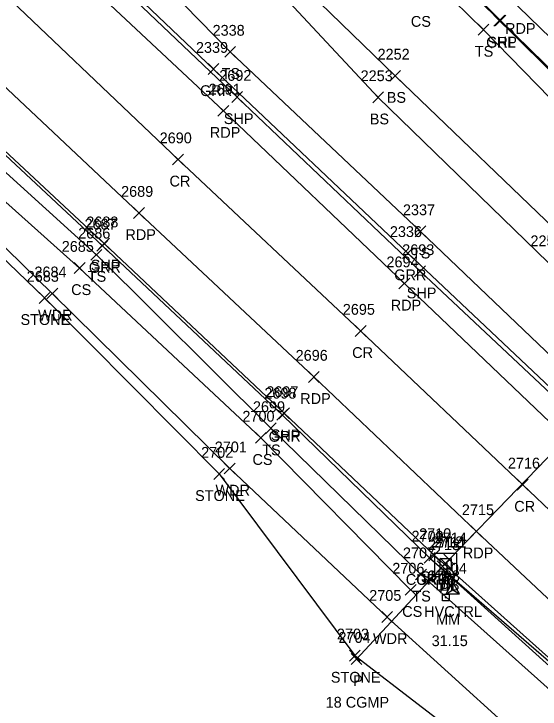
# Model space of a CAD drawing. Extents: x 1647574 to 1652703, y 212895 to 228670.
# Drawn here: x 1648450.4 to 1648547.8, y 227486.1 to 227614.7 of the extents above; entities that cross this region are included whole.
import ezdxf

# ---------------------------------------------------------------- set-up
doc = ezdxf.new("R2010")
doc.units = 0
for name, color, linetype in [('C_A', 7, 'Continuous'), ('C_I', 7, 'Continuous'), ('CPSM', 7, 'Continuous'), ('D_A', 7, 'Continuous'), ('D_C', 7, 'Continuous'), ('D_I', 7, 'Continuous'), ('D_TIC', 7, 'Continuous'), ('DCP', 7, 'Continuous'), ('DS', 7, 'Continuous'), ('L_A', 7, 'Continuous'), ('L_I', 7, 'Continuous'), ('L_TIC', 7, 'Continuous'), ('LASF', 7, 'Continuous'), ('LAWA', 7, 'Continuous'), ('LELB', 7, 'Continuous'), ('P_A', 7, 'Continuous'), ('P_I', 7, 'Continuous'), ('P_TIC', 7, 'Continuous'), ('PET', 7, 'Continuous'), ('PRC', 7, 'Continuous'), ('PSP', 7, 'Continuous'), ('R_A', 7, 'Continuous'), ('R_I', 7, 'Continuous'), ('R_TIC', 7, 'Continuous'), ('RC', 7, 'Continuous'), ('RGR', 7, 'Continuous'), ('S_A', 7, 'Continuous'), ('S_C', 7, 'Continuous'), ('S_I', 7, 'Continuous'), ('SRM', 7, 'Continuous')]:
    doc.layers.add(name, color=color, linetype=linetype)

msp = doc.modelspace()

# ---------------------------------------------------------------- linework, layer by layer
at = {"layer": 'CPSM'}
for p, q in [((1648530.44, 227507.4), (1648531.69, 227509.56)), ((1648532.94, 227507.4), (1648531.69, 227509.56)), ((1648531.69, 227508.12), (1648531.69, 227509.56)), ((1648530.44, 227507.4), (1648531.69, 227508.12)), ((1648530.44, 227507.4), (1648532.94, 227507.4)), ((1648531.69, 227508.12), (1648531.69, 227508.12)), ((1648531.69, 227508.12), (1648532.94, 227507.4))]:
    msp.add_line(p, q, dxfattribs=at)
at = {"layer": 'D_TIC'}
for points in [[(1648529.35, 227512.03), (1648531.35, 227514.03)], [(1648531.35, 227512.03), (1648529.35, 227514.03)], [(1648530, 227512.75), (1648532, 227514.75)], [(1648532, 227512.75), (1648530, 227514.75)], [(1648528.77, 227511.49), (1648530.77, 227513.49)], [(1648530.77, 227511.49), (1648528.77, 227513.49)], [(1648512.84, 227494.33), (1648514.84, 227496.33)], [(1648514.84, 227494.33), (1648512.84, 227496.33)]]:
    msp.add_lwpolyline(points, dxfattribs=at)
at = {"layer": 'DCP'}
for points in [[(1648568.95, 227553.01), (1648531, 227513.75)], [(1648513.84, 227495.33), (1648529.77, 227512.49)]]:
    msp.add_lwpolyline(points, dxfattribs=at)
at = {"layer": 'DS'}
for p, q in [((1648528.35, 227514.96), (1648532.35, 227514.96)), ((1648528.35, 227510.96), (1648528.35, 227514.96)), ((1648529.35, 227511.96), (1648529.35, 227513.96)), ((1648529.35, 227513.96), (1648531.35, 227513.96)), ((1648531.35, 227513.96), (1648531.35, 227511.96)), ((1648532.35, 227514.96), (1648532.35, 227510.96)), ((1648530.36, 227512.96), (1648530.36, 227512.96)), ((1648530.36, 227512.96), (1648530.36, 227512.96)), ((1648531.35, 227511.96), (1648529.35, 227511.96)), ((1648532.35, 227510.96), (1648528.35, 227510.96))]:
    msp.add_line(p, q, dxfattribs=at)
at = {"layer": 'L_TIC'}
for points in [[(1648536.34, 227610.83), (1648538.34, 227612.83)], [(1648538.34, 227610.83), (1648536.34, 227612.83)], [(1648489.45, 227606.71), (1648491.45, 227608.71)], [(1648491.45, 227606.71), (1648489.45, 227608.71)], [(1648520, 227602.29), (1648522, 227604.29)], [(1648522, 227602.29), (1648520, 227604.29)], [(1648516.86, 227598.3), (1648518.86, 227600.3)], [(1648518.86, 227598.3), (1648516.86, 227600.3)], [(1648524.7, 227573.49), (1648526.7, 227575.49)], [(1648526.7, 227573.49), (1648524.7, 227575.49)], [(1648464.67, 227569.17), (1648466.67, 227571.17)], [(1648466.67, 227569.17), (1648464.67, 227571.17)], [(1648461.57, 227566.71), (1648463.57, 227568.71)], [(1648463.57, 227566.71), (1648461.57, 227568.71)], [(1648456.51, 227561.98), (1648458.51, 227563.98)], [(1648458.51, 227561.98), (1648456.51, 227563.98)], [(1648455.08, 227561.17), (1648457.08, 227563.17)], [(1648457.08, 227561.17), (1648455.08, 227563.17)], [(1648496.97, 227537.04), (1648498.97, 227539.04)], [(1648498.97, 227537.04), (1648496.97, 227539.04)], [(1648495.14, 227535.27), (1648497.14, 227537.27)], [(1648497.14, 227535.27), (1648495.14, 227537.27)], [(1648487.41, 227528.59), (1648489.41, 227530.59)], [(1648489.41, 227528.59), (1648487.41, 227530.59)], [(1648489.36, 227529.59), (1648491.36, 227531.59)], [(1648491.36, 227529.59), (1648489.36, 227531.59)], [(1648524.78, 227509.98), (1648526.78, 227511.98)], [(1648526.78, 227509.98), (1648524.78, 227511.98)], [(1648522.87, 227507.14), (1648524.87, 227509.14)], [(1648524.87, 227507.14), (1648522.87, 227509.14)], [(1648518.53, 227502.11), (1648520.53, 227504.11)], [(1648520.53, 227502.11), (1648518.53, 227504.11)], [(1648512.55, 227494.96), (1648514.55, 227496.96)], [(1648514.55, 227494.96), (1648512.55, 227496.96)]]:
    msp.add_lwpolyline(points, dxfattribs=at)
at = {"layer": 'LASF'}
msp.add_lwpolyline([(1648422.89, 227594.11), (1648456.08, 227562.17), (1648488.41, 227529.59), (1648513.55, 227495.96), (1648551.12, 227467.13), (1648579.84, 227434.89), (1648625.91, 227392.57)], dxfattribs=at)
at = {"layer": 'LAWA'}
msp.add_lwpolyline([(1648247.84, 227762.38), (1648284.5, 227726.84), (1648316.68, 227694.71), (1648350.08, 227663.85), (1648386.47, 227629.65), (1648423.97, 227595.7), (1648457.51, 227562.98), (1648490.36, 227530.59), (1648519.53, 227503.11), (1648553.39, 227472.36), (1648585.36, 227442.98), (1648630.58, 227404.19)], dxfattribs=at)
at = {"layer": 'LELB'}
for points in [[(1648005.17, 228084.65), (1648023.65, 228068.5), (1648050.66, 228049.08), (1648084, 228027.44), (1648113.5, 228007.83), (1648147.29, 227982.73), (1648182.2, 227955.34), (1648213, 227923.38), (1648241.53, 227889), (1648267.07, 227861.14), (1648299.05, 227827.09), (1648330.77, 227794.94), (1648361.15, 227762.57), (1648392.5, 227731.8), (1648431.64, 227692.37), (1648464.56, 227657.5), (1648493.11, 227630.36), (1648521, 227603.29), (1648553.55, 227572.08), (1648564.74, 227563.33)], [(1648003.1, 228082.75), (1648021.4, 228065.95), (1648044.73, 228045.59), (1648079.17, 228018.19), (1648101.81, 227996.84), (1648138.98, 227971.46), (1648165.99, 227945.56), (1648168.81, 227943.47), (1648170.35, 227941.98), (1648172.46, 227939.54), (1648204.47, 227916.76), (1648236.47, 227884.75), (1648262.27, 227857.29), (1648293.8, 227821.06), (1648324.53, 227790.88), (1648359.53, 227760.77), (1648386.88, 227728.2), (1648427.75, 227689.04), (1648461.36, 227653.83), (1648490.92, 227628.14), (1648517.86, 227599.3), (1648549.31, 227568.74), (1648557.52, 227558.9)], [(1648774.58, 227389.56), (1648743.29, 227416.76), (1648711.06, 227445.83), (1648678.9, 227476.26), (1648653.94, 227498.58), (1648629.18, 227520.51), (1648599.07, 227550.48), (1648561.98, 227586.59), (1648537.34, 227611.83), (1648495.7, 227652.57), (1648469.81, 227680.64), (1648438.58, 227713.56), (1648409.77, 227744.99), (1648382.96, 227775.49), (1648351.84, 227812.3), (1648319.03, 227851.85)], [(1648685.39, 227422.2), (1648676.45, 227434.08), (1648654, 227457.48), (1648622.43, 227483.58), (1648591.46, 227513.12), (1648558.41, 227543.24), (1648525.7, 227574.49), (1648490.45, 227607.71), (1648459.18, 227639.73), (1648423.29, 227671.04), (1648396.89, 227698.59), (1648372.2, 227720.93), (1648349.64, 227747.39), (1648318.23, 227770.21)], [(1648324.38, 227700.33), (1648355.95, 227670.04), (1648394.92, 227634.14), (1648428.77, 227603.61), (1648465.67, 227570.17), (1648497.97, 227538.04), (1648525.78, 227510.98), (1648559.61, 227480.7), (1648593.98, 227451.63), (1648632.72, 227416.53), (1648638.02, 227413.49)], [(1648390.13, 227631.61), (1648425.7, 227600.61), (1648462.57, 227567.71), (1648496.14, 227536.27), (1648523.87, 227508.14)]]:
    msp.add_lwpolyline(points, dxfattribs=at)
at = {"layer": 'P_TIC'}
for points in [[(1648539.52, 227612.53), (1648541.52, 227614.53)], [(1648541.52, 227612.53), (1648539.52, 227614.53)], [(1648490.74, 227598.36), (1648492.74, 227600.36)], [(1648492.74, 227598.36), (1648490.74, 227600.36)], [(1648488.19, 227595.81), (1648490.19, 227597.81)], [(1648490.19, 227595.81), (1648488.19, 227597.81)], [(1648479.79, 227586.8), (1648481.79, 227588.8)], [(1648481.79, 227586.8), (1648479.79, 227588.8)], [(1648472.57, 227576.89), (1648474.57, 227578.89)], [(1648474.57, 227576.89), (1648472.57, 227578.89)], [(1648466.1, 227571.24), (1648468.1, 227573.24)], [(1648468.1, 227571.24), (1648466.1, 227573.24)], [(1648524.61, 227566.1), (1648526.61, 227568.1)], [(1648526.61, 227566.1), (1648524.61, 227568.1)], [(1648521.7, 227563.84), (1648523.7, 227565.84)], [(1648523.7, 227563.84), (1648521.7, 227565.84)], [(1648513.61, 227555.06), (1648515.61, 227557.06)], [(1648515.61, 227555.06), (1648513.61, 227557.06)], [(1648504.93, 227546.55), (1648506.93, 227548.55)], [(1648506.93, 227546.55), (1648504.93, 227548.55)], [(1648499.44, 227539.82), (1648501.44, 227541.82)], [(1648501.44, 227539.82), (1648499.44, 227541.82)], [(1648543.62, 227526.6), (1648545.62, 227528.6)], [(1648545.62, 227526.6), (1648543.62, 227528.6)], [(1648535.04, 227517.97), (1648537.04, 227519.97)], [(1648537.04, 227517.97), (1648535.04, 227519.97)], [(1648527.21, 227513.54), (1648529.21, 227515.54)], [(1648529.21, 227513.54), (1648527.21, 227515.54)]]:
    msp.add_lwpolyline(points, dxfattribs=at)
at = {"layer": 'PET'}
for points in [[(1648813.95, 227358.94), (1648778.04, 227392.69), (1648747.29, 227421.36), (1648716.15, 227450.61), (1648683.9, 227480.61), (1648659.12, 227504.21), (1648636.13, 227525.99), (1648605.63, 227555.48), (1648567.94, 227592.71), (1648543.86, 227616.05), (1648502.53, 227657.19), (1648475.06, 227685.79), (1648444.59, 227717.74), (1648415.43, 227749.69), (1648388.57, 227780.05), (1648357.18, 227817.31), (1648324.35, 227856.66)], [(1648315.17, 227761.11), (1648349.65, 227728.18), (1648382.59, 227697.15), (1648419.4, 227663.05), (1648452.03, 227631.59), (1648489.19, 227596.81), (1648522.7, 227564.84), (1648552.35, 227536.57), (1648584.49, 227506.14), (1648616.97, 227475.48), (1648654.44, 227439.35), (1648683.93, 227411.58), (1648698.74, 227397.7)], [(1648333.95, 227709.46), (1648364.72, 227680.29), (1648403.35, 227644.3), (1648435.48, 227613.74), (1648473.57, 227577.89), (1648505.93, 227547.55), (1648536.04, 227518.97), (1648567.27, 227489.65), (1648600.56, 227457.93), (1648638.16, 227422.42), (1648655.14, 227406.15)]]:
    msp.add_lwpolyline(points, dxfattribs=at)
at = {"layer": 'PRC'}
msp.add_lwpolyline([(1648306.81, 227751.95), (1648341.75, 227719.26), (1648373.8, 227688.7), (1648411.12, 227653.45), (1648443.57, 227623.29), (1648480.79, 227587.8), (1648514.61, 227556.06), (1648544.62, 227527.6), (1648575.8, 227497.95), (1648607.75, 227467.4), (1648646, 227431.31), (1648676.13, 227401.91)], dxfattribs=at)
at = {"layer": 'PSP'}
for points in [[(1648862.79, 227349.77), (1648859.77, 227350.01), (1648838.07, 227353.54), (1648813.95, 227358.94), (1648808.77, 227359.65), (1648801.07, 227367.02), (1648799.4, 227367.69), (1648775.51, 227390.23), (1648744.84, 227418.75), (1648714.06, 227447.93), (1648681.62, 227478.36), (1648656.94, 227501.72), (1648633.18, 227523.88), (1648602.92, 227552.91), (1648564.87, 227589.71), (1648540.52, 227613.53), (1648499.1, 227654.74), (1648471.89, 227682.44), (1648441.11, 227715.05), (1648412.29, 227746.76), (1648385.5, 227777.34), (1648354.02, 227814.19), (1648321.06, 227853.92)], [(1648318.36, 227763.01), (1648352.65, 227731.11), (1648385.57, 227699.76), (1648421.79, 227665.61), (1648455.44, 227633.9), (1648491.74, 227599.36), (1648525.61, 227567.1), (1648554.89, 227539.66), (1648587.9, 227508.74), (1648620.04, 227478.68), (1648657.86, 227443.1), (1648687.13, 227414.42), (1648699.8, 227401.85), (1648705.85, 227396.15)], [(1648327.45, 227702.95), (1648358.86, 227673.86), (1648397.53, 227637.26), (1648430.07, 227606.71), (1648467.1, 227572.24), (1648500.44, 227540.82), (1648528.21, 227514.54), (1648562.38, 227484.02), (1648596.57, 227454.64), (1648636.31, 227420.28), (1648642.1, 227415.21), (1648651.08, 227406.8), (1648655.14, 227406.15), (1648676.13, 227401.91), (1648698.74, 227397.7), (1648705.85, 227396.15)]]:
    msp.add_lwpolyline(points, dxfattribs=at)
at = {"layer": 'R_TIC'}
for points in [[(1648539.3, 227612.5), (1648541.3, 227614.5)], [(1648541.3, 227612.5), (1648539.3, 227614.5)], [(1648486.38, 227603.54), (1648488.38, 227605.54)], [(1648488.38, 227603.54), (1648486.38, 227605.54)], [(1648465.78, 227570.83), (1648467.78, 227572.83)], [(1648467.78, 227570.83), (1648465.78, 227572.83)], [(1648522.34, 227569.45), (1648524.34, 227571.45)], [(1648524.34, 227569.45), (1648522.34, 227571.45)], [(1648499.09, 227539.55), (1648501.09, 227541.55)], [(1648501.09, 227539.55), (1648499.09, 227541.55)], [(1648526.38, 227513.07), (1648528.38, 227515.07)], [(1648528.38, 227513.07), (1648526.38, 227515.07)], [(1648526.38, 227513.07), (1648528.38, 227515.07)], [(1648528.38, 227513.07), (1648526.38, 227515.07)]]:
    msp.add_lwpolyline(points, dxfattribs=at)
at = {"layer": 'RC'}
msp.add_lwpolyline([(1648527.38, 227514.07), (1648596.32, 227454.39), (1648636.06, 227420.08), (1648641.29, 227415.63)], dxfattribs=at)
at = {"layer": 'RGR'}
for points in [[(1648799.4, 227367.69), (1648775.21, 227390.09), (1648744.67, 227418.58), (1648713.63, 227447.71), (1648681.41, 227478.1), (1648656.75, 227501.4), (1648632.98, 227523.33), (1648602.41, 227552.12), (1648564.56, 227589.41), (1648540.3, 227613.5), (1648498.82, 227654.38), (1648471.44, 227682.07), (1648440.86, 227714.66), (1648411.81, 227746.44), (1648384.97, 227776.71), (1648353.62, 227813.75), (1648320.77, 227853.11)], [(1648697.72, 227405.66), (1648692.45, 227411.09), (1648683.98, 227419.76), (1648672.37, 227430.57), (1648663.53, 227439.76), (1648649.68, 227452.69), (1648619.08, 227481.01), (1648588.86, 227509.07), (1648555.34, 227540.28), (1648523.34, 227570.45), (1648487.38, 227604.54), (1648455.36, 227635), (1648420.16, 227668.08), (1648392.98, 227694.22), (1648369.01, 227717), (1648345.96, 227742.52)], [(1648327.16, 227702.7), (1648358.85, 227673.4), (1648397.37, 227637.01), (1648429.81, 227606.31), (1648466.78, 227571.83), (1648500.09, 227540.55), (1648527.38, 227514.07), (1648561.67, 227483.12), (1648595.98, 227454.16), (1648635.83, 227419.79), (1648639.15, 227416.04)]]:
    msp.add_lwpolyline(points, dxfattribs=at)
at = {"layer": 'SRM'}
msp.add_lwpolyline([(1648529.75, 227507.35), (1648531, 227507.35), (1648531, 227506.1), (1648529.75, 227506.1)], close=True, dxfattribs=at)
msp.add_circle((1648530.37, 227506.72), 0.0833, dxfattribs=at)

# ---------------------------------------------------------------- texts
at = {"layer": 'C_A'}
msp.add_text('HVCTRL', height=2, dxfattribs=at).set_placement((1648526.38, 227503.12))
at = {"layer": 'C_I'}
msp.add_text('104', height=2, dxfattribs=at).set_placement((1648529.82, 227511.12))
at = {"layer": 'D_A'}
for s, p in [('DIB', (1648528.45, 227508.03)), ('DI', (1648529.41, 227507.96)), ('P', (1648530.38, 227508.75)), ('P', (1648529.15, 227507.49)), ('P', (1648513.22, 227490.33))]:
    msp.add_text(s, height=2, dxfattribs=at).set_placement(p)
at = {"layer": 'D_C'}
msp.add_text('18 CGMP', height=2, dxfattribs=at).set_placement((1648508.13, 227486.33))
at = {"layer": 'D_I'}
for s, p in [('2712', (1648527.66, 227516.03)), ('2711', (1648528.23, 227515.96)), ('2714', (1648528.31, 227516.75)), ('2713', (1648527.08, 227515.49)), ('2704', (1648510.5, 227498.33))]:
    msp.add_text(s, height=2, dxfattribs=at).set_placement(p)
at = {"layer": 'L_A'}
for s, p in [('CS', (1648523.91, 227612.36)), ('TS', (1648535.75, 227606.83)), ('TS', (1648488.86, 227602.71)), ('BS', (1648519.44, 227598.29)), ('BS', (1648516.3, 227594.3)), ('TS', (1648524.11, 227569.49)), ('TS', (1648464.08, 227565.17)), ('CS', (1648461.01, 227562.71)), ('STONE', (1648451.63, 227557.17)), ('WDR', (1648454.87, 227557.98)), ('TS', (1648496.38, 227533.04)), ('CS', (1648494.58, 227531.27)), ('STONE', (1648483.95, 227524.59)), ('WDR', (1648487.73, 227525.59)), ('TS', (1648524.19, 227505.98)), ('CS', (1648522.31, 227503.14)), ('WDR', (1648516.89, 227498.11)), ('STONE', (1648509.09, 227490.96))]:
    msp.add_text(s, height=2, dxfattribs=at).set_placement(p)
at = {"layer": 'L_I'}
for s, p in [('2338', (1648487.19, 227610.71)), ('2252', (1648517.74, 227606.29)), ('2253', (1648514.6, 227602.3)), ('2337', (1648522.44, 227577.49)), ('2686', (1648462.31, 227573.17)), ('2254', (1648546.05, 227571.74)), ('2685', (1648459.26, 227570.71)), ('2684', (1648454.2, 227565.98)), ('2683', (1648452.78, 227565.17)), ('2699', (1648494.66, 227541.04)), ('2700', (1648492.71, 227539.27)), ('2701', (1648487.59, 227533.59)), ('2702', (1648485.07, 227532.59)), ('2707', (1648522.44, 227513.98)), ('2706', (1648520.47, 227511.14)), ('2705', (1648516.19, 227506.11)), ('2703', (1648510.21, 227498.96))]:
    msp.add_text(s, height=2, dxfattribs=at).set_placement(p)
at = {"layer": 'P_A'}
for s, p in [('RDP', (1648541.35, 227611.05)), ('SHP', (1648538.05, 227608.53)), ('SHP', (1648489.27, 227594.36)), ('RDP', (1648486.68, 227591.81)), ('CR', (1648479.22, 227582.8)), ('RDP', (1648471.05, 227572.89)), ('SHP', (1648464.64, 227567.24)), ('SHP', (1648523.14, 227562.1)), ('RDP', (1648520.18, 227559.84)), ('CR', (1648513.04, 227551.06)), ('RDP', (1648503.42, 227542.55)), ('SHP', (1648497.97, 227535.82)), ('CR', (1648543.05, 227522.6)), ('RDP', (1648533.53, 227513.97)), ('SHP', (1648525.74, 227509.54))]:
    msp.add_text(s, height=2, dxfattribs=at).set_placement(p)
at = {"layer": 'P_I'}
for s, p in [('2692', (1648488.43, 227602.36)), ('2691', (1648486.45, 227599.81)), ('2690', (1648477.39, 227590.8)), ('2689', (1648470.25, 227580.89)), ('2688', (1648463.8, 227575.24)), ('2693', (1648522.3, 227570.1)), ('2694', (1648519.39, 227567.84)), ('2695', (1648511.3, 227559.06)), ('2696', (1648502.57, 227550.55)), ('2697', (1648497.13, 227543.82)), ('2716', (1648541.87, 227530.6)), ('2715', (1648533.35, 227521.97)), ('2710', (1648525.43, 227517.54))]:
    msp.add_text(s, height=2, dxfattribs=at).set_placement(p)
at = {"layer": 'R_A'}
for s, p in [('GRL', (1648537.85, 227608.5)), ('GRR', (1648484.87, 227599.54)), ('GRR', (1648464.27, 227566.83)), ('GRR', (1648520.83, 227565.45)), ('GRR', (1648497.58, 227535.55)), ('CURBB', (1648522.96, 227509.07)), ('GRR', (1648524.87, 227509.07))]:
    msp.add_text(s, height=2, dxfattribs=at).set_placement(p)
at = {"layer": 'R_I'}
for s, p in [('2339', (1648484.11, 227607.54)), ('2687', (1648463.48, 227574.83)), ('2336', (1648520.02, 227573.45)), ('2698', (1648496.78, 227543.55)), ('2709', (1648524.03, 227517.07)), ('2709', (1648524.03, 227517.07))]:
    msp.add_text(s, height=2, dxfattribs=at).set_placement(p)
at = {"layer": 'S_A'}
msp.add_text('MM', height=2, dxfattribs=at).set_placement((1648528.56, 227501.72))
at = {"layer": 'S_C'}
msp.add_text('31.15', height=2, dxfattribs=at).set_placement((1648527.76, 227497.72))
at = {"layer": 'S_I'}
msp.add_text('2708', height=2, dxfattribs=at).set_placement((1648527.03, 227509.72))

doc.saveas('drawing.dxf')
